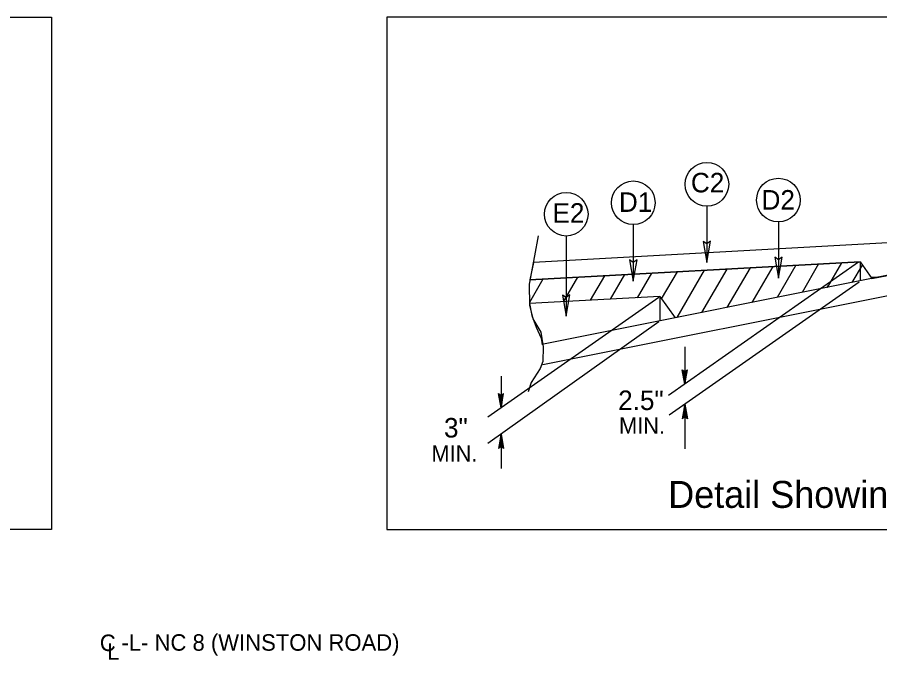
# Model space of a CAD drawing. Extents: x 957297 to 961629, y 830661 to 840840.
# Drawn here: x 959449.4 to 959855.8, y 840068.3 to 840370.7 of the extents above; entities that cross this region are included whole.
import ezdxf

# ---------------------------------------------------------------- set-up
doc = ezdxf.new("R2010")
doc.units = 0
for name, color, linetype in [('Old_Level_1', 7, 'Continuous'), ('Prop Dimension Text', 7, 'Continuous'), ('Typical Detail Wedge1 CELL', 7, 'Continuous'), ('Typical ID Circle CELL', 7, 'Continuous'), ('Typical Terminator CELL', 7, 'Continuous'), ('Typical Text General CELL', 7, 'Continuous'), ('Typical Text ID Circle CELL', 7, 'Continuous')]:
    doc.layers.add(name, color=color, linetype=linetype)

msp = doc.modelspace()

# ---------------------------------------------------------------- linework, layer by layer
at = {"layer": 'Old_Level_1'}
for points in [[(958940.99, 840370.75), (959465.55, 840370.75), (959465.55, 840129.62), (958940.99, 840129.62)], [(960249.58, 840370.75), (959623.52, 840370.75), (959623.52, 840129.62), (960249.58, 840129.62)]]:
    msp.add_lwpolyline(points, close=True, dxfattribs=at)
at = {"layer": 'Typical Detail Wedge1 CELL'}
for p, q in [((959925.21, 840268.1), (959692.59, 840255.33)), ((959925.21, 840268.1), (959692.59, 840255.33)), ((959925.21, 840262.34), (959697.32, 840216.87)), ((959852.13, 840247.71), (959925.21, 840262.34)), ((959846.53, 840255.64), (959690.94, 840247.1)), ((959690.94, 840247.1), (959846.53, 840255.64)), ((959692.59, 840255.33), (959690.94, 840247.1)), ((959845.86, 840255.38), (959756.24, 840192.61)), ((959816.24, 840253.99), (959807.4, 840238.84)), ((959827.02, 840254.58), (959819.22, 840241.19)), ((959837.8, 840255.17), (959831.02, 840243.54)), ((959842.84, 840245.9), (959847.62, 840254.1)), ((959846.53, 840255.64), (959852.13, 840247.71)), ((959846.53, 840255.64), (959846.53, 840246.65)), ((959846.53, 840255.64), (959852.13, 840247.71)), ((959925.21, 840252.71), (959697.03, 840207.06)), ((959748.32, 840250.25), (959741.58, 840238.68)), ((959760.31, 840250.91), (959752.89, 840238.2)), ((959773.11, 840251.61), (959760.16, 840229.42)), ((959771.98, 840231.78), (959783.9, 840252.2)), ((959794.68, 840252.8), (959783.78, 840234.12)), ((959805.46, 840253.39), (959795.6, 840236.48)), ((959697.14, 840247.43), (959690.72, 840236.44)), ((959713.33, 840248.33), (959706.61, 840236.81)), ((959726.13, 840249.03), (959719.4, 840237.49)), ((959735.54, 840249.57), (959728.79, 840237.99)), ((959846.03, 840245.96), (959756.6, 840183.35)), ((959854.83, 840248.43), (959851.74, 840248.26)), ((959831.02, 840243.54), (959831.42, 840244.25)), ((959751.72, 840238.75), (959671.17, 840182.44)), ((959752.15, 840239.24), (959690.73, 840235.96)), ((959752.15, 840239.24), (959759.38, 840229.26)), ((959752.15, 840239.24), (959752.15, 840227.86)), ((959690.73, 840235.96), (959691.88, 840230.31)), ((959691.88, 840230.31), (959693.95, 840224.81)), ((959751.72, 840227.35), (959671.2, 840170.12)), ((959693.95, 840224.81), (959696.35, 840219.66)), ((959696.35, 840219.66), (959696.69, 840216.57)), ((959763.96, 840215.54), (959763.96, 840198.02)), ((959677.41, 840201.7), (959677.41, 840186.8)), ((959763.96, 840198.02), (959762.77, 840204.78)), ((959762.77, 840204.78), (959763.96, 840203.9)), ((959762.94, 840204.65), (959763.96, 840198.02)), ((959763.96, 840198.02), (959763.11, 840204.53)), ((959763.28, 840204.4), (959763.96, 840198.02)), ((959763.96, 840198.02), (959763.45, 840204.27)), ((959763.62, 840204.16), (959763.96, 840198.02)), ((959763.96, 840198.02), (959763.79, 840204.04)), ((959763.96, 840198.02), (959765.16, 840204.78)), ((959763.96, 840203.9), (959765.16, 840204.78)), ((959763.96, 840198.02), (959764.98, 840204.65)), ((959764.81, 840204.53), (959763.96, 840198.02)), ((959763.96, 840198.02), (959764.64, 840204.4)), ((959764.47, 840204.27), (959763.96, 840198.02)), ((959763.96, 840198.02), (959764.3, 840204.16)), ((959764.13, 840204.04), (959763.96, 840198.02)), ((959763.96, 840203.9), (959763.96, 840198.02)), ((959677.41, 840186.8), (959676.21, 840193.56)), ((959676.21, 840193.56), (959677.41, 840192.68)), ((959676.38, 840193.44), (959677.41, 840186.8)), ((959677.41, 840186.8), (959676.55, 840193.31)), ((959676.72, 840193.18), (959677.41, 840186.8)), ((959677.41, 840186.8), (959676.88, 840193.06)), ((959677.41, 840186.8), (959678.6, 840193.56)), ((959677.41, 840192.68), (959678.6, 840193.56)), ((959677.41, 840186.8), (959678.42, 840193.44)), ((959678.25, 840193.31), (959677.41, 840186.8)), ((959677.41, 840186.8), (959678.08, 840193.18)), ((959677.92, 840193.06), (959677.41, 840186.8)), ((959677.05, 840192.94), (959677.41, 840186.8)), ((959677.41, 840186.8), (959677.22, 840192.81)), ((959677.41, 840186.8), (959677.75, 840192.94)), ((959677.58, 840192.81), (959677.41, 840186.8)), ((959677.41, 840192.68), (959677.41, 840186.8)), ((959763.96, 840188.51), (959762.77, 840181.74)), ((959763.96, 840188.51), (959762.94, 840181.87)), ((959763.11, 840182), (959763.96, 840188.51)), ((959763.96, 840188.51), (959763.28, 840182.12)), ((959763.45, 840182.25), (959763.96, 840188.51)), ((959763.96, 840188.51), (959763.62, 840182.38)), ((959763.79, 840182.5), (959763.96, 840188.51)), ((959763.96, 840188.51), (959763.96, 840167.54)), ((959763.96, 840188.51), (959765.15, 840181.74)), ((959764.98, 840181.87), (959763.96, 840188.51)), ((959763.96, 840188.51), (959764.81, 840182)), ((959764.64, 840182.12), (959763.96, 840188.51)), ((959763.96, 840188.51), (959764.47, 840182.25)), ((959764.3, 840182.38), (959763.96, 840188.51)), ((959763.96, 840188.51), (959764.13, 840182.5)), ((959763.96, 840182.63), (959763.96, 840188.51)), ((959763.96, 840182.63), (959762.77, 840181.74)), ((959765.15, 840181.74), (959763.96, 840182.63)), ((959677.41, 840174.46), (959676.21, 840167.7)), ((959677.41, 840174.46), (959676.38, 840167.83)), ((959676.55, 840167.95), (959677.41, 840174.46)), ((959677.41, 840174.46), (959676.72, 840168.08)), ((959676.88, 840168.21), (959677.41, 840174.46)), ((959677.41, 840174.46), (959677.05, 840168.33)), ((959677.22, 840168.45), (959677.41, 840174.46)), ((959677.41, 840174.46), (959677.41, 840158.27)), ((959677.41, 840174.46), (959678.59, 840167.7)), ((959678.42, 840167.83), (959677.41, 840174.46)), ((959677.41, 840174.46), (959678.25, 840167.95)), ((959678.08, 840168.08), (959677.41, 840174.46)), ((959677.41, 840174.46), (959677.92, 840168.21)), ((959677.75, 840168.33), (959677.41, 840174.46)), ((959677.41, 840174.46), (959677.58, 840168.45)), ((959677.41, 840168.59), (959677.41, 840174.46)), ((959677.41, 840168.59), (959676.21, 840167.7)), ((959678.59, 840167.7), (959677.41, 840168.59))]:
    msp.add_line(p, q, dxfattribs=at)
msp.add_lwpolyline([(959694.93, 840267.83), (959693.19, 840258.37), (959690.55, 840245.13), (959690.75, 840235.12), (959692.38, 840228.81), (959696.06, 840222.48), (959697.28, 840215.54), (959697.07, 840208.61), (959695.85, 840205.34), (959691.57, 840198.81), (959690.14, 840194.32)], dxfattribs=at)
at = {"layer": 'Typical ID Circle CELL'}
for p, q in [((959774.36, 840281.82), (959774.36, 840255.27)), ((959808.03, 840274.4), (959808.03, 840247.86)), ((959739.68, 840273.12), (959739.68, 840246.57)), ((959708.08, 840267.75), (959708.08, 840230))]:
    msp.add_line(p, q, dxfattribs=at)
for centre in [(959774.36, 840292.09), (959808.03, 840284.67), (959739.69, 840283.39), (959708.08, 840278.01)]:
    msp.add_circle(centre, 10.27, dxfattribs=at)
at = {"layer": 'Typical Terminator CELL'}
for points in [[(959772.64, 840265.23), (959774.36, 840255.27), (959776.13, 840265.29), (959774.36, 840264.02)], [(959737.97, 840256.53), (959739.68, 840246.57), (959741.45, 840256.59), (959739.68, 840255.31)], [(959737.97, 840256.53), (959739.68, 840246.57), (959741.45, 840256.59), (959739.68, 840255.31)], [(959806.31, 840257.82), (959808.03, 840247.86), (959809.8, 840257.87), (959808.03, 840256.6)], [(959806.31, 840257.82), (959808.03, 840247.86), (959809.8, 840257.87), (959808.03, 840256.6)], [(959706.37, 840239.96), (959708.08, 840230), (959709.85, 840240.02), (959708.08, 840238.74)]]:
    msp.add_lwpolyline(points, close=True, dxfattribs=at)

# ---------------------------------------------------------------- texts
at = {"layer": 'Prop Dimension Text'}
for s, height, p in [('C', 7.77, (959488.35, 840072.34)), ('-L- NC 8 (WINSTON ROAD)', 7.7675, (959498.55, 840072.49)), ('-L- ', 7.767, (959498.55, 840072.49)), ('L', 7.77, (959491.74, 840068.25))]:
    msp.add_text(s, height=height, rotation=0, dxfattribs=at).set_placement(p)
at = {"layer": 'Typical Detail Wedge1 CELL'}
for p in [(959732.96, 840174.64), (959644.56, 840161.58)]:
    msp.add_text('MIN.', height=7.683, dxfattribs=at).set_placement(p)
at = {"layer": 'Typical Text General CELL'}
msp.add_text('Detail Showing Method Of Wedging No. 2', height=12.6816, dxfattribs=at).set_placement((959756.13, 840139.75))
at = {"layer": 'Typical Text ID Circle CELL'}
for s, p in [('C2', (959766.84, 840288.3)), ('D1', (959732.92, 840279.12)), ('D2', (959800.12, 840280.19)), ('E2', (959701.62, 840274.02)), ('2.5"', (959732.55, 840185.82)), ('3"', (959650.5, 840172.89))]:
    msp.add_text(s, height=9.194, dxfattribs=at).set_placement(p)

doc.saveas('drawing.dxf')
